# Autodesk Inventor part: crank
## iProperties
Created: 2009-04
Part Number: crank
Document SubType Name: Modeling
Designer: Lochan
Density: 1 g/cm^3
Author: Lochan
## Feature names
1. Extrusion1
2. Extrusion2
3. Revolution1
